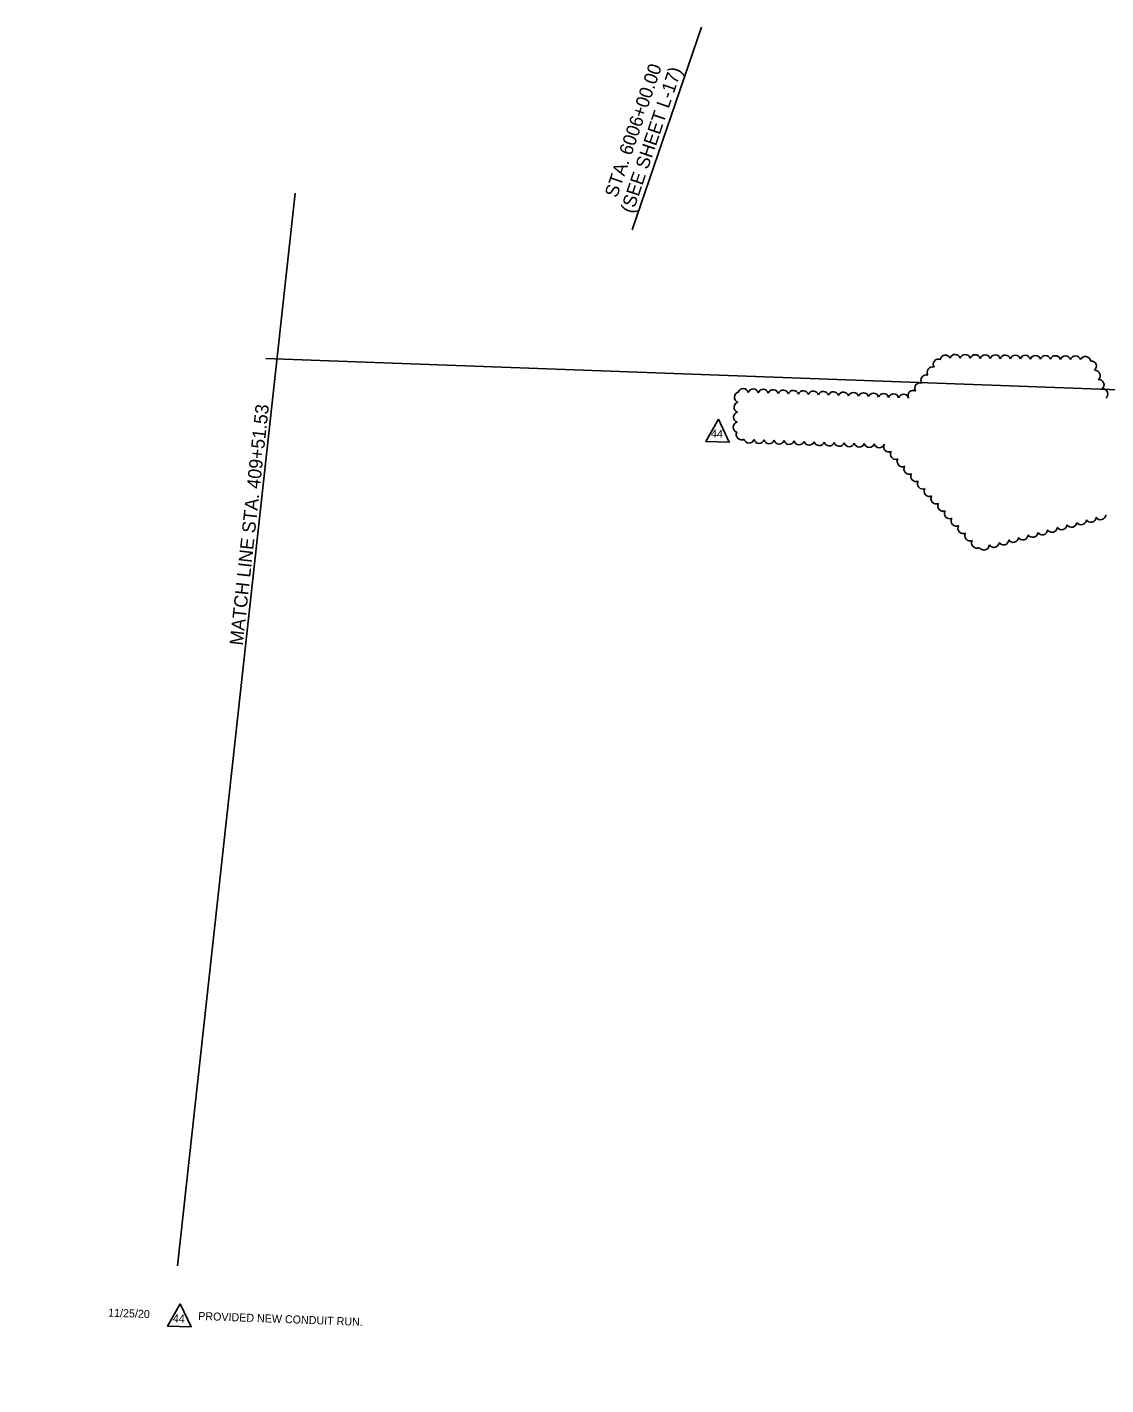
# Model space of a CAD drawing. Extents: x 919231 to 920524, y 636539 to 637379.
# Drawn here: x 919231 to 919878, y 636564 to 637379 of the extents above; entities that cross this region are included whole.
import ezdxf

# ---------------------------------------------------------------- set-up
doc = ezdxf.new("R2010")
doc.units = 0
for name, color, linetype in [('ActivePointCell_dp', 7, 'Continuous'), ('AdhocPoint_dp', 7, 'Continuous'), ('Cloud_dp', 7, 'Continuous'), ('MatchLines_dp', 7, 'Continuous')]:
    doc.layers.add(name, color=color, linetype=linetype)

msp = doc.modelspace()

# ---------------------------------------------------------------- linework, layer by layer
at = {"layer": 'ActivePointCell_dp'}
msp.add_line((919374.23, 637180.22), (920419.17, 637141.7), dxfattribs=at)
at = {"layer": 'AdhocPoint_dp'}
msp.add_line((919231.07, 636564.45), (919231.07, 636564.45), dxfattribs=at)
at = {"layer": 'Cloud_dp'}
for points in [[(919645.75, 637143.81), (919638.21, 637130.52), (919652.28, 637130)], [(919322.89, 636613.01), (919315.35, 636599.72), (919329.43, 636599.2)]]:
    msp.add_lwpolyline(points, close=True, dxfattribs=at)
for centre, radius, start, end in [((919781.99, 637179.16), 3.1, 25.50383, 170.50383), ((919787.82, 637179.5), 3.19, 16.79862, 161.79862), ((919793.86, 637179.43), 3.15, 16.79862, 161.79862), ((919799.88, 637179.36), 3.15, 16.79862, 161.79862), ((919805.89, 637179.29), 3.15, 16.79862, 161.79862), ((919811.91, 637179.21), 3.15, 16.79862, 161.79862), ((919817.92, 637179.14), 3.15, 16.79862, 161.79862), ((919823.94, 637179.07), 3.15, 16.79862, 161.79862), ((919829.95, 637178.99), 3.15, 16.79862, 161.79862), ((919835.97, 637178.92), 3.15, 16.79862, 161.79862), ((919841.98, 637178.84), 3.15, 16.79862, 161.79862), ((919848, 637178.77), 3.15, 16.79862, 161.79862), ((919854.01, 637178.7), 3.15, 16.79862, 161.79862), ((919860.03, 637178.62), 3.15, 16.79862, 161.79862), ((919865.98, 637178.16), 3.24, 9.84984, 154.84984), ((919774.13, 637171.98), 3.15, 69.51319, 214.51319), ((919777.84, 637176.72), 3.15, 69.51319, 214.51319), ((919869.44, 637175.59), 3.13, 309.77549, 94.77549), ((919871.71, 637170.04), 3.15, 309.77549, 94.77549), ((919766.73, 637162.5), 3.15, 69.51319, 214.51319), ((919770.43, 637167.23), 3.15, 69.51319, 214.51319), ((919873.99, 637164.47), 3.15, 309.77549, 94.77549), ((919658.54, 637157.01), 3.15, 105.38886, 250.38886), ((919660.67, 637159), 3.15, 15.51057, 160.51057), ((919666.68, 637158.79), 3.15, 15.51057, 160.51057), ((919672.7, 637158.58), 3.15, 15.51057, 160.51057), ((919678.71, 637158.37), 3.15, 15.51057, 160.51057), ((919684.72, 637158.16), 3.15, 15.51057, 160.51057), ((919690.73, 637157.95), 3.15, 15.51057, 160.51057), ((919696.74, 637157.75), 3.15, 15.51057, 160.51057), ((919702.75, 637157.54), 3.15, 15.51057, 160.51057), ((919708.77, 637157.33), 3.15, 15.51057, 160.51057), ((919714.78, 637157.12), 3.15, 15.51057, 160.51057), ((919720.79, 637156.91), 3.15, 15.51057, 160.51057), ((919726.8, 637156.7), 3.15, 15.51057, 160.51057), ((919732.81, 637156.49), 3.15, 15.51057, 160.51057), ((919738.82, 637156.28), 3.15, 15.51057, 160.51057), ((919744.84, 637156.08), 3.15, 15.51057, 160.51057), ((919750.85, 637155.87), 3.15, 15.51057, 160.51057), ((919756.86, 637155.66), 3.15, 15.51057, 160.51057), ((919762.68, 637157.94), 3.13, 62.31669, 207.31669), ((919876.27, 637158.91), 3.15, 309.77549, 94.77549), ((919658.31, 637151), 3.15, 105.38886, 250.38886), ((919657.87, 637138.98), 3.15, 105.38886, 250.38886), ((919658.09, 637144.99), 3.15, 105.38886, 250.38886), ((919659.62, 637134.61), 3.14, 153.5403, 298.5403), ((919664.18, 637132.69), 3.17, 195.38886, 340.38886), ((919670.2, 637132.46), 3.15, 195.38886, 340.38886), ((919676.21, 637132.24), 3.15, 195.38886, 340.38886), ((919682.22, 637132.02), 3.15, 195.38886, 340.38886), ((919688.23, 637131.8), 3.15, 195.38886, 340.38886), ((919694.25, 637131.58), 3.15, 195.38886, 340.38886), ((919700.26, 637131.36), 3.15, 195.38886, 340.38886), ((919706.27, 637131.13), 3.15, 195.38886, 340.38886), ((919712.28, 637130.91), 3.15, 195.38886, 340.38886), ((919718.29, 637130.69), 3.15, 195.38886, 340.38886), ((919724.3, 637130.47), 3.15, 195.38886, 340.38886), ((919730.31, 637130.25), 3.15, 195.38886, 340.38886), ((919736.32, 637130.03), 3.15, 195.38886, 340.38886), ((919742.33, 637129.8), 3.15, 195.38886, 340.38886), ((919748.05, 637127.25), 3.13, 151.44811, 296.44811), ((919752.17, 637122.86), 3.15, 149.76839, 294.76839), ((919756.22, 637118.41), 3.15, 149.76839, 294.76839), ((919760.26, 637113.96), 3.15, 149.76839, 294.76839), ((919764.31, 637109.51), 3.15, 149.76839, 294.76839), ((919768.35, 637105.06), 3.15, 149.76839, 294.76839), ((919772.4, 637100.61), 3.15, 149.76839, 294.76839), ((919776.44, 637096.16), 3.15, 149.76839, 294.76839), ((919780.49, 637091.7), 3.15, 149.76839, 294.76839), ((919784.54, 637087.25), 3.15, 149.76839, 294.76839), ((919788.58, 637082.8), 3.15, 149.76839, 294.76839), ((919863.44, 637083.59), 3.15, 211.96915, 356.96915), ((919869.26, 637085.1), 3.15, 211.96915, 356.96915), ((919875.09, 637086.6), 3.15, 211.96915, 356.96915), ((919792.63, 637078.35), 3.15, 149.76839, 294.76839), ((919796.67, 637073.9), 3.15, 149.76839, 294.76839), ((919834.32, 637076.08), 3.15, 211.96915, 356.96915), ((919840.14, 637077.58), 3.15, 211.96915, 356.96915), ((919845.97, 637079.09), 3.15, 211.96915, 356.96915), ((919851.79, 637080.59), 3.15, 211.96915, 356.96915), ((919857.61, 637082.09), 3.15, 211.96915, 356.96915), ((919800.82, 637069.62), 3.16, 153.38559, 298.38559), ((919805.09, 637068.57), 3.26, 211.96915, 356.96915), ((919811.02, 637070.07), 3.15, 211.96915, 356.96915), ((919816.84, 637071.57), 3.15, 211.96915, 356.96915), ((919822.67, 637073.07), 3.15, 211.96915, 356.96915), ((919828.49, 637074.58), 3.15, 211.96915, 356.96915)]:
    msp.add_arc(centre, radius, start, end, dxfattribs=at)
at = {"layer": 'MatchLines_dp'}
for p, q in [((919635.67, 637379.02), (919594.14, 637257.46)), ((919391.9, 637279.39), (919321.22, 636635.78))]:
    msp.add_line(p, q, dxfattribs=at)

# ---------------------------------------------------------------- texts
at = {"layer": 'Cloud_dp'}
for s, p in [('44', (919641.27, 637132.82)), ('11/25/20', (919279.6, 636605.42)), ('44', (919318.41, 636602.02)), ('PROVIDED NEW CONDUIT RUN.', (919333.63, 636603.43))]:
    msp.add_text(s, height=4.8, rotation=357.88886, dxfattribs=at).set_placement(p)
at = {"layer": 'MatchLines_dp'}
for s, rotation, p in [('STA. 6006+00.00', 71.13417, (919584.92, 637276.27)), ('(SEE SHEET L-17) ', 71.13417, (919594.38, 637266.84)), (' MATCH LINE STA. 409+51.53', 83.76428, (919360.09, 637004.85))]:
    msp.add_text(s, height=8, rotation=rotation, dxfattribs=at).set_placement(p)

doc.saveas('drawing.dxf')
